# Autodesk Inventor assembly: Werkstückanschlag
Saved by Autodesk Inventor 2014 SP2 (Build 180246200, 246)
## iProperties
Created: 2015-07
Part Number: Werkstückanschlag
Document SubType Name: Assembly
Designer: e_krauts
Author: e_krauts
Sending System: SolidWorks 2011
Last Author: e_boekem
Sachnummer: NWS 100-00-00
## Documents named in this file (10)
- Z:\VDW-Nachwuchsstiftung Intern\Mitarbeiter Ablage\Steffen Krauth\IVCAM\Werkstückanschlag\Imported Components\Werkstückanschlag\Werkstückanschlag.iam
- Z:\VDW-Nachwuchsstiftung Intern\Mitarbeiter Ablage\Steffen Krauth\IVCAM\Werkstückanschlag\Imported Components\Werkstückanschlag\Seitenteil.ipt
- Z:\VDW-Nachwuchsstiftung Intern\Mitarbeiter Ablage\Steffen Krauth\IVCAM\Werkstückanschlag\Imported Components\Werkstückanschlag\Fuß.ipt
- Z:\VDW-Nachwuchsstiftung Intern\Mitarbeiter Ablage\Steffen Krauth\IVCAM\Werkstückanschlag\Imported Components\Werkstückanschlag\Bolzen.ipt
- Z:\VDW-Nachwuchsstiftung Intern\Mitarbeiter Ablage\Steffen Krauth\IVCAM\Werkstückanschlag\Imported Components\Werkstückanschlag\Bolzen_Bolzen mit Gewinde.ipt
- Z:\VDW-Nachwuchsstiftung Intern\Mitarbeiter Ablage\Steffen Krauth\IVCAM\Werkstückanschlag\Imported Components\Werkstückanschlag\Nadelhalterung.ipt
- Z:\VDW-Nachwuchsstiftung Intern\Mitarbeiter Ablage\Steffen Krauth\IVCAM\Werkstückanschlag\Imported Components\Werkstückanschlag\Nadelhalterung_Nadelhalterung Oberteil.ipt
- Z:\VDW-Nachwuchsstiftung Intern\Mitarbeiter Ablage\Steffen Krauth\IVCAM\Werkstückanschlag\Imported Components\Werkstückanschlag\Anschlagsnadel.ipt
- Z:\VDW-Nachwuchsstiftung Intern\Mitarbeiter Ablage\Steffen Krauth\IVCAM\Werkstückanschlag\Imported Components\Werkstückanschlag\Zylinderschraube ISO 4762 M8 x 55.ipt
- Z:\VDW-Nachwuchsstiftung Intern\Mitarbeiter Ablage\Steffen Krauth\IVCAM\Werkstückanschlag\Imported Components\Werkstückanschlag\Zylinderschraube ISO 10642 - M5 x 30.ipt
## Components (13 placed, 7 different names)
1. Seitenteil:1
2. Seitenteil:3
3. Fuß:1
4. Fuß:3
5. Bolzen:1
6. Bolzen:3
7. Nadelhalterung:1
8. Nadelhalterung:2
9. Anschlagsnadel:1
10. Zylinderschraube ISO 4762 M8 x 55:1
11. Zylinderschraube ISO 10642 - M5 x 30:1
12. Zylinderschraube ISO 4762 M8 x 55:2
13. Zylinderschraube ISO 10642 - M5 x 30:2
